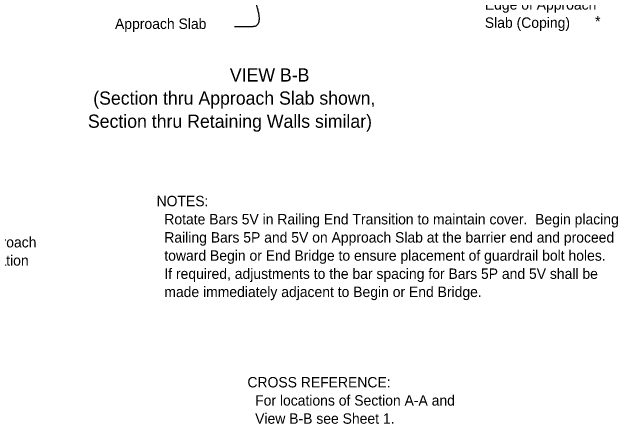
# Model space of a CAD drawing. Extents: x 130539.2 to 130573.7, y 88651.8 to 88671.1.
# Drawn here: x 130551.23 to 130557.09, y 88659.12 to 88663.11 of the extents above; entities that cross this region are included whole.
import ezdxf

# ---------------------------------------------------------------- set-up
doc = ezdxf.new("R2010")
doc.units = 0
doc.layers.add('Dimension', color=7, linetype='Continuous')
doc.layers.add('TextStructures', color=7, linetype='Continuous')

msp = doc.modelspace()

# ---------------------------------------------------------------- linework, layer by layer
at = {"layer": 'Dimension'}
msp.add_open_spline([(130553.3789, 88662.9747), (130553.4967, 88662.9747), (130553.6188, 88662.9747), (130553.6188, 88663.1274), (130553.5272, 88663.3673)], degree=2, dxfattribs=at)

# ---------------------------------------------------------------- texts
for s, p in [('Edge of Approach', (130555.8009, 88663.1362)), ('Approach Slab', (130552.2219, 88662.9495)), ('Slab (Coping)', (130555.8009, 88662.9602)), ('NOTES:', (130552.6241, 88661.2317)), ('  Rotate Bars 5V in Railing End Transition to maintain cover.  Begin placing ', (130552.6241, 88661.0557)), ('Begin or End Approach ', (130550.0675, 88660.8326)), ('  Railing Bars 5P and 5V on Approach Slab at the barrier end and proceed ', (130552.6241, 88660.8797)), ('Slab or limiting station ', (130550.0675, 88660.6566)), ('  toward Begin or End Bridge to ensure placement of guardrail bolt holes.  ', (130552.6241, 88660.7037)), ('  If required, adjustments to the bar spacing for Bars 5P and 5V shall be ', (130552.6241, 88660.5277)), ('  made immediately adjacent to Begin or End Bridge.', (130552.6241, 88660.3517)), ('CROSS REFERENCE:', (130553.5032, 88659.4762)), ('  For locations of Section A-A and ', (130553.5032, 88659.3002)), ('  View B-B see Sheet 1.', (130553.5032, 88659.1242))]:
    msp.add_text(s, height=0.1008, dxfattribs=at).set_placement(p)
at = {"layer": 'TextStructures'}
for s, height, p in [('*', 0.1008, (130556.8674, 88662.9727)), ('VIEW B-B', 0.128, (130553.3331, 88662.4396)), ('(Section thru Approach Slab shown,', 0.128, (130552.011, 88662.2156)), ('Section thru Retaining Walls similar)', 0.128, (130551.9594, 88661.9916))]:
    msp.add_text(s, height=height, dxfattribs=at).set_placement(p)

doc.saveas('drawing.dxf')
